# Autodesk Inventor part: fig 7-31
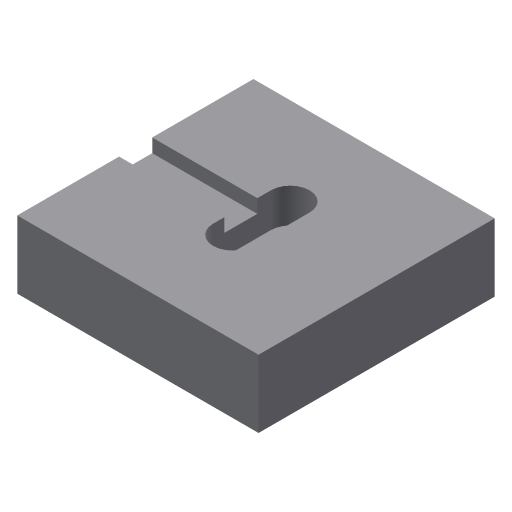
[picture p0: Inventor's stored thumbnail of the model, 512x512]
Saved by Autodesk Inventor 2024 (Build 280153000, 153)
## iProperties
Created: 2004-05
Part Number: fig 7-31
Document SubType Name: Modeling
Designer: CADCIM Technologies
Manufacturer: Standard
Standards Organization: Custom
Density: 1 g/cm^3
Material: Generic
Appearance: Default
Author: CADCIM Technologies
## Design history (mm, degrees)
sketch "Sketch1"
  geometry: L1 (-30.233, -25.517)-(22.302, -25.517); L2 (22.302, -25.517)-(22.302, 25.904); L3 (22.302, 25.904)-(-30.233, 25.904); L4 (-30.233, 25.904)-(-30.233, -25.517)
  constraints: 8 end point, 2 parallel, 1 horizontal, 1 perpendicular
extrude "Extrusion1" new body sketch "Sketch1" distance "d0" = 14.75; taper "d1" = 0 deg
sketch "Sketch2"
  geometry: L1 (1.047, -5.75)-(1.047, 6.846); L2 (-7.35, 6.845)-(-7.35, -5.75); A1 r 4.198 centre (-3.152, 6.846) between (1.047, 6.846) and (-7.35, 6.845); A2 r 4.198 centre (-3.152, -5.75) between (-7.35, -5.75) and (1.047, -5.75)
  constraints: 4 end point, 4 point on circle, 4 tangent, 2 centre point, 1 parallel
extrude "Extrusion2" cut sketch "Sketch2" distance "d2" = 7.5; taper "d3" = 0 deg
sketch "Sketch3"
  geometry: L1 (-7.5, 0)-(-7.5, 12.595) reference; L2 (-7.5, 0)-(0, 0) reference; L3 (-7.5, 2.416)-(-4.537, 2.416); L4 (-4.537, 2.416)-(-4.537, 9.616); L5 (-4.537, 9.616)-(-7.5, 9.616)
  constraints: 6 end point, 2 perpendicular, 2 point on line, 1 parallel
extrude "Extrusion3" cut sketch "Sketch3" extent not by distance; stored distance "d4" = 6.75; taper "d5" = 0 deg
body "Solid1"
